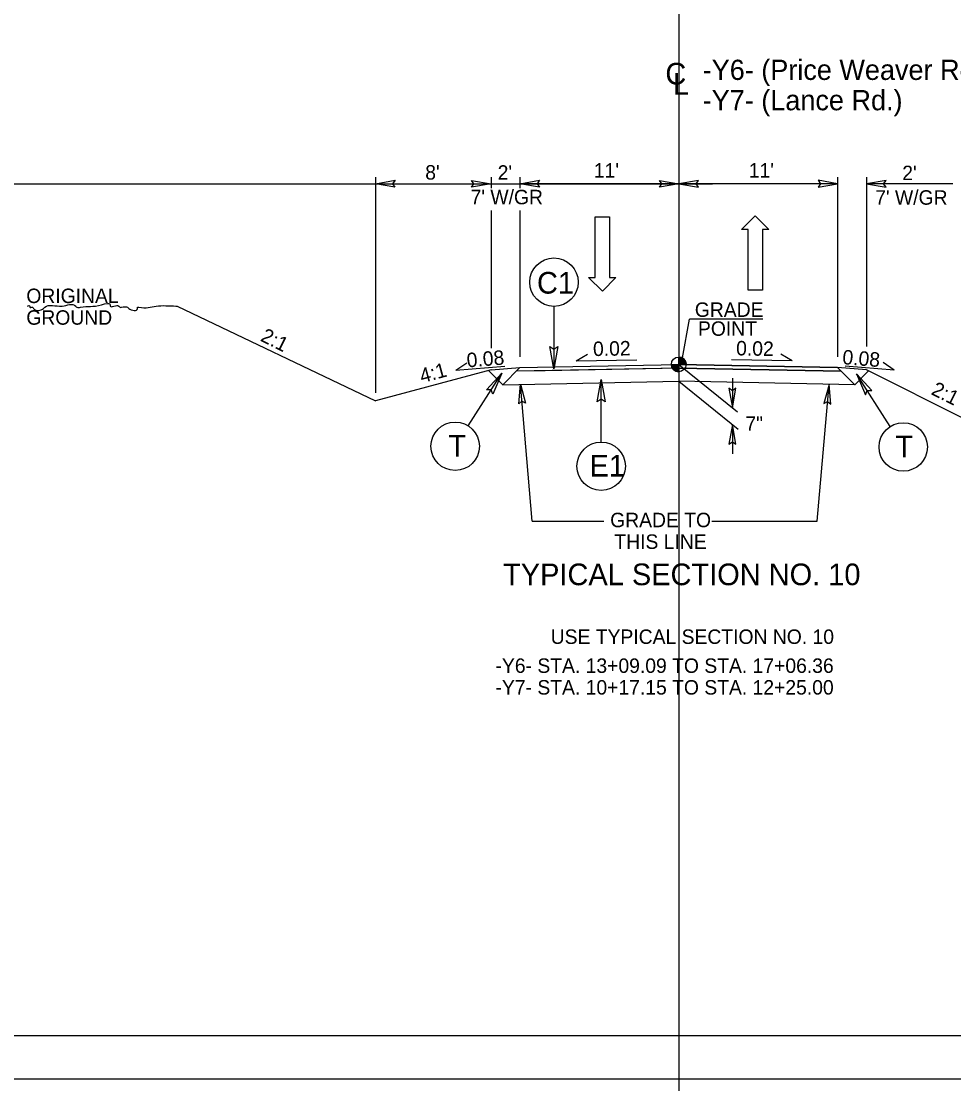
# Model space of a CAD drawing. Extents: x 18938 to 19565, y 6931 to 7973.
# Drawn here: x 19282.1 to 19346.7, y 7371.6 to 7445.2 of the extents above; entities that cross this region are included whole.
import ezdxf

# ---------------------------------------------------------------- set-up
doc = ezdxf.new("R2010")
doc.units = 0
for name, color, linetype in [('Old_Level_11', 7, 'Continuous'), ('Old_Level_2', 7, 'Continuous'), ('Old_Level_3', 7, 'Continuous'), ('Prop Dimension', 7, 'Continuous'), ('Prop Pavement Schedule Description CELL', 7, 'Continuous'), ('Prop Shade Medium', 7, 'Continuous'), ('Prop Terminator CELL', 7, 'Continuous'), ('Sheet Data Field CELL', 7, 'Continuous'), ('Sheet Plot Border Outside CELL', 7, 'Continuous'), ('Sheet Typical CELL', 7, 'Continuous'), ('Typical Curb CELL', 7, 'Continuous'), ('Typical Detail Wedge1 CELL', 7, 'Continuous'), ('Typical Detail Wedge2 CELL', 7, 'Continuous'), ('Typical Detail Wedge3 CELL', 7, 'Continuous'), ('Typical Guardrail CELL', 7, 'Continuous'), ('Typical Hinge Slope Arterial CELL', 7, 'Continuous'), ('Typical Pavement Slope Information CELL', 7, 'Continuous'), ('Typical Shoulder Slope Information CELL', 7, 'Continuous'), ('Typical Terminator CELL', 7, 'Continuous'), ('Typical Text General CELL', 7, 'Continuous'), ('Typical Text Grade Point CELL', 7, 'Continuous'), ('Typical Text ID Circle CELL', 7, 'Continuous'), ('Typical Text Label CELL', 7, 'Continuous')]:
    doc.layers.add(name, color=color, linetype=linetype)

msp = doc.modelspace()

# ---------------------------------------------------------------- linework, layer by layer
at = {"layer": 'Old_Level_3'}
msp.add_line((19314.658, 7433.942), (19316.658, 7433.942), dxfattribs=at)
at = {"layer": 'Prop Dimension'}
msp.add_lwpolyline([(19155.167, 7371.975), (19382.434, 7371.975), (19382.434, 7518.408), (19155.167, 7518.408)], close=True, dxfattribs=at)
at = {"layer": 'Prop Pavement Schedule Description CELL'}
for p, q in [((19316.658, 7421.217), (19327.659, 7421.437)), ((19338.658, 7421.217), (19327.658, 7421.437)), ((19315.468, 7420.027), (19314.484, 7421.01)), ((19314.658, 7421.057), (19316.658, 7421.217)), ((19315.468, 7420.027), (19316.658, 7421.217)), ((19327.659, 7421.187), (19316.403, 7420.962)), ((19327.659, 7421.187), (19338.913, 7420.962)), ((19340.658, 7421.057), (19338.658, 7421.217)), ((19339.849, 7420.027), (19338.658, 7421.217)), ((19339.849, 7420.027), (19340.806, 7420.984)), ((19347.46, 7417.657), (19340.658, 7421.057)), ((19315.468, 7420.027), (19327.658, 7420.271)), ((19320.158, 7420.125), (19320.158, 7420.121)), ((19339.849, 7420.027), (19327.658, 7420.271)), ((19335.158, 7420.125), (19335.158, 7420.121))]:
    msp.add_line(p, q, dxfattribs=at)
at = {"layer": 'Prop Shade Medium'}
for p in [(19292.925, 7425.478), (19314.658, 7421.057)]:
    msp.add_line(p, (19306.658, 7418.908), dxfattribs=at)
at = {"layer": 'Sheet Data Field CELL'}
for points in [[(19308.008, 7433.71), (19306.658, 7433.942), (19308.016, 7434.182), (19307.843, 7433.942)], [(19313.308, 7434.175), (19314.658, 7433.942), (19313.301, 7433.702), (19313.473, 7433.942)], [(19313.308, 7434.175), (19314.658, 7433.942), (19313.301, 7433.702), (19313.473, 7433.942)], [(19318.008, 7433.71), (19316.658, 7433.942), (19318.016, 7434.182), (19317.843, 7433.942)], [(19326.323, 7434.175), (19327.673, 7433.942), (19326.316, 7433.702), (19326.488, 7433.942)], [(19329.023, 7434.175), (19327.673, 7433.942), (19329.031, 7433.702), (19328.858, 7433.942)], [(19337.308, 7433.71), (19338.658, 7433.942), (19337.301, 7434.182), (19337.473, 7433.942)], [(19342.008, 7434.175), (19340.658, 7433.942), (19342.016, 7433.702), (19341.843, 7433.942)], [(19316.576, 7418.713), (19316.692, 7420.078), (19317.048, 7418.747), (19316.794, 7418.898)], [(19338.184, 7418.687), (19338.07, 7420.052), (19337.713, 7418.72), (19337.967, 7418.871)], [(19331.135, 7419.783), (19331.368, 7418.433), (19331.608, 7419.79), (19331.368, 7419.618)], [(19331.6, 7415.916), (19331.367, 7417.266), (19331.127, 7415.909), (19331.367, 7416.081)]]:
    msp.add_lwpolyline(points, close=True, dxfattribs=at)
at = {"layer": 'Sheet Typical CELL'}
for p, q in [((19306.658, 7434.403), (19306.658, 7419.477)), ((19306.658, 7433.942), (19314.658, 7433.942)), ((19314.658, 7434.403), (19314.658, 7433.642)), ((19316.658, 7434.403), (19316.658, 7433.642)), ((19338.658, 7433.942), (19316.658, 7433.942)), ((19338.658, 7434.403), (19338.658, 7421.957)), ((19340.658, 7434.403), (19340.658, 7422.674)), ((19346.628, 7433.942), (19340.658, 7433.942)), ((19314.658, 7432.08), (19314.658, 7422.557)), ((19316.658, 7432.089), (19316.658, 7421.957)), ((19327.659, 7421.437), (19331.714, 7418.152)), ((19317.511, 7410.592), (19316.692, 7420.078)), ((19327.658, 7420.271), (19331.763, 7416.946)), ((19331.368, 7420.476), (19331.368, 7418.433)), ((19337.243, 7410.592), (19338.07, 7420.052)), ((19331.367, 7417.266), (19331.367, 7415.243)), ((19317.511, 7410.592), (19322.471, 7410.592)), ((19329.949, 7410.592), (19337.243, 7410.592))]:
    msp.add_line(p, q, dxfattribs=at)
at = {"layer": 'Typical Curb CELL'}
msp.add_spline([(19282.561, 7425.478), (19282.732, 7425.478), (19282.732, 7425.392), (19282.903, 7425.392), (19282.989, 7425.306), (19283.674, 7425.306), (19283.76, 7425.392), (19284.959, 7425.478), (19285.901, 7425.478), (19285.987, 7425.392), (19286.244, 7425.392), (19287.7, 7425.564), (19288.3, 7425.564), (19288.3, 7425.478), (19288.899, 7425.478), (19288.985, 7425.392), (19289.071, 7425.392), (19289.499, 7425.392), (19289.585, 7425.306), (19290.184, 7425.306), (19290.184, 7425.392), (19290.27, 7425.392), (19291.469, 7425.478), (19292.839, 7425.478), (19292.925, 7425.478)], degree=3, dxfattribs=at)
at = {"layer": 'Typical Detail Wedge1 CELL'}
for p, q in [((19327.146, 7421.437), (19327.659, 7421.437)), ((19327.658, 7420.925), (19327.659, 7421.437)), ((19327.659, 7421.437), (19327.658, 7420.925)), ((19327.659, 7421.437), (19327.659, 7421.949)), ((19328.17, 7421.437), (19327.659, 7421.437))]:
    msp.add_line(p, q, dxfattribs=at)
for points in [[(19327.149, 7421.437), (19327.149, 7421.381)], [(19327.16, 7421.437), (19327.16, 7421.321)], [(19327.17, 7421.437), (19327.17, 7421.284)], [(19327.18, 7421.437), (19327.18, 7421.254)], [(19327.19, 7421.437), (19327.19, 7421.229)], [(19327.2, 7421.437), (19327.2, 7421.208)], [(19327.211, 7421.437), (19327.211, 7421.188)], [(19327.221, 7421.437), (19327.221, 7421.171)], [(19327.231, 7421.437), (19327.231, 7421.155)], [(19327.242, 7421.437), (19327.242, 7421.14)], [(19327.252, 7421.437), (19327.252, 7421.126)], [(19327.262, 7421.437), (19327.262, 7421.113)], [(19327.272, 7421.437), (19327.272, 7421.101)], [(19327.283, 7421.437), (19327.283, 7421.089)], [(19327.293, 7421.437), (19327.293, 7421.079)], [(19327.303, 7421.437), (19327.303, 7421.069)], [(19327.313, 7421.437), (19327.313, 7421.059)], [(19327.324, 7421.437), (19327.323, 7421.05)], [(19327.334, 7421.437), (19327.334, 7421.041)], [(19327.344, 7421.437), (19327.344, 7421.033)], [(19327.354, 7421.437), (19327.354, 7421.025)], [(19327.364, 7421.437), (19327.364, 7421.018)], [(19327.375, 7421.437), (19327.374, 7421.011)], [(19327.385, 7421.437), (19327.385, 7421.004)], [(19327.395, 7421.437), (19327.395, 7420.998)], [(19327.405, 7421.437), (19327.405, 7420.992)], [(19327.415, 7421.437), (19327.415, 7420.986)], [(19327.426, 7421.437), (19327.426, 7420.981)], [(19327.436, 7421.437), (19327.436, 7420.976)], [(19327.446, 7421.437), (19327.446, 7420.971)], [(19327.457, 7421.437), (19327.457, 7420.967)], [(19327.467, 7421.437), (19327.467, 7420.962)], [(19327.477, 7421.437), (19327.477, 7420.958)], [(19327.488, 7421.437), (19327.488, 7420.955)], [(19327.498, 7421.437), (19327.498, 7420.951)], [(19327.508, 7421.437), (19327.508, 7420.948)], [(19327.518, 7421.437), (19327.518, 7420.945)], [(19327.528, 7421.437), (19327.528, 7420.942)], [(19327.539, 7421.437), (19327.538, 7420.94)], [(19327.549, 7421.437), (19327.549, 7420.937)], [(19327.559, 7421.437), (19327.559, 7420.935)], [(19327.569, 7421.437), (19327.569, 7420.933)], [(19327.579, 7421.437), (19327.579, 7420.931)], [(19327.59, 7421.437), (19327.59, 7420.93)], [(19327.6, 7421.437), (19327.6, 7420.928)], [(19327.61, 7421.437), (19327.61, 7420.927)], [(19327.62, 7421.437), (19327.62, 7420.927)], [(19327.631, 7421.437), (19327.631, 7420.926)], [(19327.641, 7421.437), (19327.641, 7420.925)], [(19327.651, 7421.437), (19327.651, 7420.925), (19327.651, 7420.925)], [(19327.663, 7421.949), (19327.663, 7421.949), (19327.663, 7421.437)], [(19327.674, 7421.949), (19327.673, 7421.437)], [(19327.684, 7421.948), (19327.684, 7421.437)], [(19327.694, 7421.948), (19327.694, 7421.437)], [(19327.704, 7421.947), (19327.704, 7421.437)], [(19327.715, 7421.946), (19327.715, 7421.437)], [(19327.725, 7421.945), (19327.725, 7421.437)], [(19327.735, 7421.943), (19327.735, 7421.437)], [(19327.746, 7421.942), (19327.745, 7421.437)], [(19327.756, 7421.94), (19327.756, 7421.437)], [(19327.766, 7421.938), (19327.766, 7421.437)], [(19327.776, 7421.935), (19327.776, 7421.437)], [(19327.787, 7421.933), (19327.786, 7421.437)], [(19327.797, 7421.93), (19327.797, 7421.437)], [(19327.807, 7421.927), (19327.807, 7421.437)], [(19327.817, 7421.924), (19327.817, 7421.437)], [(19327.828, 7421.921), (19327.827, 7421.437)], [(19327.838, 7421.917), (19327.837, 7421.437)], [(19327.848, 7421.913), (19327.848, 7421.437)], [(19327.858, 7421.909), (19327.858, 7421.437)], [(19327.868, 7421.904), (19327.868, 7421.437)], [(19327.878, 7421.899), (19327.878, 7421.437)], [(19327.889, 7421.895), (19327.889, 7421.437)], [(19327.899, 7421.889), (19327.899, 7421.437)], [(19327.909, 7421.883), (19327.909, 7421.437)], [(19327.919, 7421.877), (19327.919, 7421.437)], [(19327.93, 7421.871), (19327.93, 7421.437)], [(19327.94, 7421.865), (19327.94, 7421.437)], [(19327.95, 7421.858), (19327.95, 7421.437)], [(19327.961, 7421.851), (19327.961, 7421.437)], [(19327.971, 7421.843), (19327.971, 7421.437)], [(19327.981, 7421.835), (19327.981, 7421.437)], [(19327.991, 7421.826), (19327.991, 7421.437)], [(19328.002, 7421.817), (19328.001, 7421.437)], [(19328.012, 7421.808), (19328.012, 7421.437)], [(19328.022, 7421.798), (19328.022, 7421.437)], [(19328.032, 7421.787), (19328.032, 7421.437)], [(19328.042, 7421.776), (19328.042, 7421.437)], [(19328.053, 7421.764), (19328.052, 7421.437)], [(19328.063, 7421.751), (19328.063, 7421.437)], [(19328.073, 7421.737), (19328.073, 7421.437)], [(19328.083, 7421.723), (19328.083, 7421.437)], [(19328.093, 7421.707), (19328.093, 7421.437)], [(19328.104, 7421.69), (19328.104, 7421.437)], [(19328.114, 7421.671), (19328.114, 7421.437)], [(19328.124, 7421.649), (19328.124, 7421.437)], [(19328.135, 7421.625), (19328.135, 7421.437)], [(19328.145, 7421.597), (19328.145, 7421.437)], [(19328.155, 7421.562), (19328.155, 7421.437)], [(19328.165, 7421.51), (19328.165, 7421.437)]]:
    msp.add_lwpolyline(points, dxfattribs=at)
msp.add_circle((19327.658, 7421.437), 0.512, dxfattribs=at)
for start, end in [(179.99048, 269.99048), (359.99048, 89.99048)]:
    msp.add_arc((19327.658, 7421.437), 0.512, start, end, dxfattribs=at)
at = {"layer": 'Typical Detail Wedge3 CELL'}
for p, q in [((19321.865, 7427.456), (19321.865, 7431.656)), ((19321.865, 7431.656), (19322.855, 7431.656)), ((19322.855, 7431.656), (19322.855, 7427.456)), ((19332.011, 7430.785), (19332.941, 7431.73)), ((19332.941, 7431.73), (19333.901, 7430.785)), ((19332.461, 7430.785), (19332.011, 7430.785)), ((19332.461, 7426.585), (19332.461, 7430.785)), ((19333.901, 7430.785), (19333.451, 7430.785)), ((19333.451, 7430.785), (19333.451, 7426.585)), ((19322.375, 7426.511), (19321.415, 7427.456)), ((19321.415, 7427.456), (19321.865, 7427.456)), ((19323.305, 7427.456), (19322.375, 7426.511)), ((19322.855, 7427.456), (19323.305, 7427.456)), ((19333.451, 7426.585), (19332.461, 7426.585))]:
    msp.add_line(p, q, dxfattribs=at)
at = {"layer": 'Typical Guardrail CELL'}
for p, q in [((19327.658, 7635.751), (19327.658, 7292.693)), ((19202.089, 7433.94), (19329.987, 7433.94))]:
    msp.add_line(p, q, dxfattribs=at)
at = {"layer": 'Typical Hinge Slope Arterial CELL'}
for p, q in [((19316.658, 7421.217), (19327.659, 7421.437)), ((19327.659, 7421.437), (19338.658, 7421.217)), ((19316.403, 7420.962), (19316.658, 7421.217)), ((19318.403, 7421.002), (19316.403, 7420.962)), ((19327.659, 7421.187), (19318.403, 7421.002)), ((19318.403, 7421.002), (19318.403, 7421.002)), ((19338.913, 7420.962), (19327.659, 7421.187)), ((19338.658, 7421.217), (19338.913, 7420.962))]:
    msp.add_line(p, q, dxfattribs=at)
at = {"layer": 'Typical Pavement Slope Information CELL'}
msp.add_lwpolyline([(19380.142, 7515.401), (19177.642, 7515.401), (19177.642, 7374.986), (19380.142, 7374.986)], close=True, dxfattribs=at)
at = {"layer": 'Typical Terminator CELL'}
for p, q in [((19319.016, 7425.451), (19319.016, 7421.12)), ((19313.074, 7417.183), (19315.4, 7420.836)), ((19342.3, 7417.136), (19339.974, 7420.79)), ((19322.283, 7416.064), (19322.283, 7420.395))]:
    msp.add_line(p, q, dxfattribs=at)
for centre in [(19319.016, 7427.127), (19312.174, 7415.77), (19343.2, 7415.723), (19322.283, 7414.388)]:
    msp.add_circle(centre, 1.676, dxfattribs=at)
at = {"layer": 'Typical Text General CELL'}
for points in [[(19319.283, 7422.672), (19319.016, 7421.12), (19318.74, 7422.68), (19319.016, 7422.482)], [(19314.341, 7419.671), (19315.4, 7420.836), (19314.795, 7419.372), (19314.668, 7419.687)], [(19341.033, 7419.624), (19339.974, 7420.79), (19340.579, 7419.325), (19340.705, 7419.641)], [(19322.016, 7418.843), (19322.283, 7420.395), (19322.559, 7418.835), (19322.283, 7419.033)]]:
    msp.add_lwpolyline(points, close=True, dxfattribs=at)
at = {"layer": 'Typical Text Grade Point CELL'}
for p, q in [((19320.563, 7421.677), (19321.346, 7422.151)), ((19335.507, 7421.677), (19334.724, 7422.151)), ((19312.226, 7421.038), (19312.979, 7421.557)), ((19312.226, 7421.038), (19315.612, 7421.309)), ((19320.563, 7421.677), (19324.751, 7421.761)), ((19335.507, 7421.677), (19331.318, 7421.761)), ((19342.564, 7421.046), (19339.178, 7421.316)), ((19342.564, 7421.046), (19341.811, 7421.565))]:
    msp.add_line(p, q, dxfattribs=at)
at = {"layer": 'Typical Text ID Circle CELL'}
for p, q in [((19327.658, 7438.879), (19327.658, 7433.942)), ((19327.658, 7433.942), (19327.658, 7417.701)), ((19327.908, 7421.89), (19328.404, 7424.558)), ((19333.481, 7424.558), (19328.404, 7424.558))]:
    msp.add_line(p, q, dxfattribs=at)

# ---------------------------------------------------------------- texts
at = {"layer": 'Old_Level_11'}
for s, height, p in [('TYPICAL SECTION NO. 10', 1.5, (19315.495, 7406.152)), ('USE TYPICAL SECTION NO. 10', 1, (19318.789, 7402.088))]:
    msp.add_text(s, height=height, dxfattribs=at).set_placement(p)
at = {"layer": 'Old_Level_2'}
for s, p in [('ORIGINAL', (19282.484, 7425.684)), ('GROUND', (19282.484, 7424.184))]:
    msp.add_text(s, height=1, rotation=360, dxfattribs=at).set_placement(p)
at = {"layer": 'Prop Terminator CELL'}
for s, p in [('C1', (19317.842, 7426.338)), ('T', (19342.656, 7415.003)), ('E1', (19321.475, 7413.677))]:
    msp.add_text(s, height=1.5, dxfattribs=at).set_placement(p)
msp.add_text('T', height=1.5, rotation=360, dxfattribs=at).set_placement((19311.705, 7415.05))
at = {"layer": 'Sheet Plot Border Outside CELL'}
for s, p in [('GRADE', (19328.769, 7424.727)), ('POINT', (19328.987, 7423.416))]:
    msp.add_text(s, height=1, rotation=0.00004, dxfattribs=at).set_placement(p)
at = {"layer": 'Typical Detail Wedge2 CELL'}
for s, p in [("11'", (19321.779, 7434.37)), ("11'", (19332.503, 7434.37)), ("8'", (19310.104, 7434.232)), ("2'", (19315.119, 7434.222)), ("2'", (19343.133, 7434.192)), ("7' W/GR", (19313.243, 7432.522)), ("7' W/GR", (19341.257, 7432.492)), ('7"', (19332.27, 7416.839)), ('GRADE TO', (19322.908, 7410.167)), ('THIS LINE', (19323.199, 7408.667)), ('-Y6- STA. 13+09.09 TO STA. 17+06.36', (19314.97, 7400.082)), ('-Y7- STA. 10+17.15 TO STA. 12+25.00', (19314.97, 7398.582))]:
    msp.add_text(s, height=1, dxfattribs=at).set_placement(p)
at = {"layer": 'Typical Shoulder Slope Information CELL'}
for s, rotation, p in [('2:1', 333.43491, (19298.634, 7423.1)), ('4:1', 15.1346, (19309.874, 7420.133)), ('2:1', 333.43491, (19345.071, 7419.396))]:
    msp.add_text(s, height=1, rotation=rotation, dxfattribs=at).set_placement(p)
at = {"layer": 'Typical Text Grade Point CELL'}
for s, rotation, p in [('0.02', 1.14574, (19321.73, 7422.012)), ('0.02', 358.85426, (19331.622, 7422.067)), ('0.08', 4.5738, (19313.014, 7421.226)), ('0.08', 355.4262, (19338.96, 7421.459))]:
    msp.add_text(s, height=1, rotation=rotation, dxfattribs=at).set_placement(p)
at = {"layer": 'Typical Text Label CELL'}
for s, height, p in [('C', 1.5, (19326.729, 7440.814)), ('-Y6- (Price Weaver Rd.)', 1.4, (19329.314, 7441.129)), ('L', 1.5, (19327.246, 7440.107)), ('-Y7- (Lance Rd.)', 1.4, (19329.314, 7439.029))]:
    msp.add_text(s, height=height, dxfattribs=at).set_placement(p)

doc.saveas('drawing.dxf')
